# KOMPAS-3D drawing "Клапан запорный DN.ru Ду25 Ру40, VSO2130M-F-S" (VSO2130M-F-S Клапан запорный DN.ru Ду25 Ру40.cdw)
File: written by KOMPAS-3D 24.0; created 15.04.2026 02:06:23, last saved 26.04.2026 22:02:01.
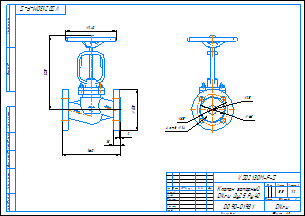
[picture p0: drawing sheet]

Document properties: Автор: DN.ru; Форматы листов документа: A3; Полное имя файла: VSO2130M-F-S Клапан запорный DN.ru Ду25 Ру40.m3d; Масса: 5.5; Наименование: Клапан запорный DN.ru Ду25 Ру40; Количество листов документа: 1; Примечание: D090-01981

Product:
- Part/product: Клапан запорный DN.ru Ду25 Ру40  | designation VSO2130M-F-S
    Масса: 5.5
    Раздел спецификации: Прочие изделия
    Примечание: D090-01981

Views: Вид 1, Вид:1, Проекционный вид 2
Referenced files in C:\Работа\VSO2130M-F-S Клапан запорный DN.ru\DN15\: VSO2130M-F-S DN15 PN40  Клапан запорный сильфонный DN.ru.m3d
Referenced files in C:\Работа\VSO2130M-F-S Клапан запорный DN.ru Ду-x Ру40\DN25\: VSO2130M-F-S Клапан запорный DN.ru Ду25 Ру40.m3d
Referenced files in C:\Program Files\ASCON\KOMPAS-3D v24\Templates\: Чертеж_DN.ru.cdt
Referenced files in C:\Работа\ГОТОВЫЕ ИСХОДНИКИ\VSO2130M-F-S Клапан запорный сальниковый DN.ru Ду15-100 Ру40\DN25\: VSO2130M-F-S Клапан запорный DN.ru Ду25 Ру40.m3d
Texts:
  VSO2130M-F-S
  Чертеж_DN.ru.cdt
  Клапан запорный
  DN.ru Ду25 Ру40
  Клапан запорный DN.ru Ду25 Ру40
  VSO2130M-F-S Клапан запорный DN.ru Ду25 Ру40
Dimensions and other numbers on the sheet: 0; 3; 2; 4; 115; 18; 205; 140; 160; 5; 25; 68; 85; 4 отв.; 14; 1:2; 1; 5,5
